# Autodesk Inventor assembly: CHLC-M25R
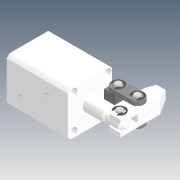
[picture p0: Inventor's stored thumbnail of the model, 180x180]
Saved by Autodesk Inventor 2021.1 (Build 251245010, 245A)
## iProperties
Company: Microsoft
Created: 2019-11
Part Number: CHLC-M25R
Description: STEP AP214
Document SubType Name: Assembly
Designer: user
Title: CHLC-M25R.STEP
Author: Windows
Revision Number: ÈÎºÎ
Sending System: SolidWorks 2015
Preprocessor: SwSTEP 2.0
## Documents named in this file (10)
- D:\Vault_2016\Projekty\Clamptek\Hydraulic\CHLC\CHLC-25\Inventor\CHLC-M25R\CHLC-M25R.iam
- D:\Vault_2016\Projekty\Clamptek\Hydraulic\CHLC\CHLC-25\Inventor\CHLC-M25R\CHLC-25LG.ipt
- D:\Vault_2016\Projekty\Clamptek\Hydraulic\CHLC\CHLC-25\Inventor\CHLC-M25R\CHLC-25HSG.ipt
- D:\Vault_2016\Projekty\Clamptek\Hydraulic\CHLC\CHLC-25\Inventor\CHLC-M25R\CHLC-25DX.ipt
- D:\Vault_2016\Projekty\Clamptek\Hydraulic\CHLC\CHLC-25\Inventor\CHLC-M25R\CHLC-25CX.ipt
- D:\Vault_2016\Projekty\Clamptek\Hydraulic\CHLC\CHLC-25\Inventor\CHLC-M25R\CHLC-25KKDC.ipt
- D:\Vault_2016\Projekty\Clamptek\Hydraulic\CHLC\CHLC-25\Inventor\CHLC-M25R\chlc-m25bt.ipt
- D:\Vault_2016\Projekty\Clamptek\Hydraulic\CHLC\CHLC-25\Inventor\CHLC-M25R\socket set screw cup point_iso_ISO 4029 - M5 x 6-N.ipt
- D:\Vault_2016\Projekty\Clamptek\Hydraulic\CHLC\CHLC-25\Inventor\CHLC-M25R\CHLC-25ZC.ipt
- D:\Vault_2016\Projekty\Clamptek\Hydraulic\CHLC\CHLC-25\Inventor\CHLC-M25R\Ñ¹±Û.ipt
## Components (17 placed, 17 different names)
1. CHLC-25LG_1
2. CHLC-25LG_2
3. CHLC-25HSG_3
4. CHLC-25DX_4
5. CHLC-25CX_5
6. CHLC-25CX_6
7. CHLC-25KKDC_7
8. CHLC-25KKDC_8
9. CHLC-25KKDC_9
10. CHLC-25KKDC_10
11. CHLC-25KKDC_11
12. CHLC-25KKDC_12
13. chlc-m25bt_13
14. socket set screw cup point_iso_ISO 4029 - M5 x 6-N_14
15. socket set screw cup point_iso_ISO 4029 - M5 x 6-N_15
16. CHLC-25ZC_16
17. Ñ¹±Û_17
